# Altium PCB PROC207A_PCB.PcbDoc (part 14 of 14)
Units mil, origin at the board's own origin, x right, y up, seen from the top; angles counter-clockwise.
Board outline 4094.49 x 3724.79 mil, 8 copper layers (Top Layer, L2_GND1, L3_SIG1, L4_PWR1, L5_PWR2, L6_SIG2, L7_GND2, Bottom Layer), stack 58.1 mil thick; 584 components, 399 nets, 8440 pads, 5258 vias.
Unrouted connection lines stored in the file: 9.
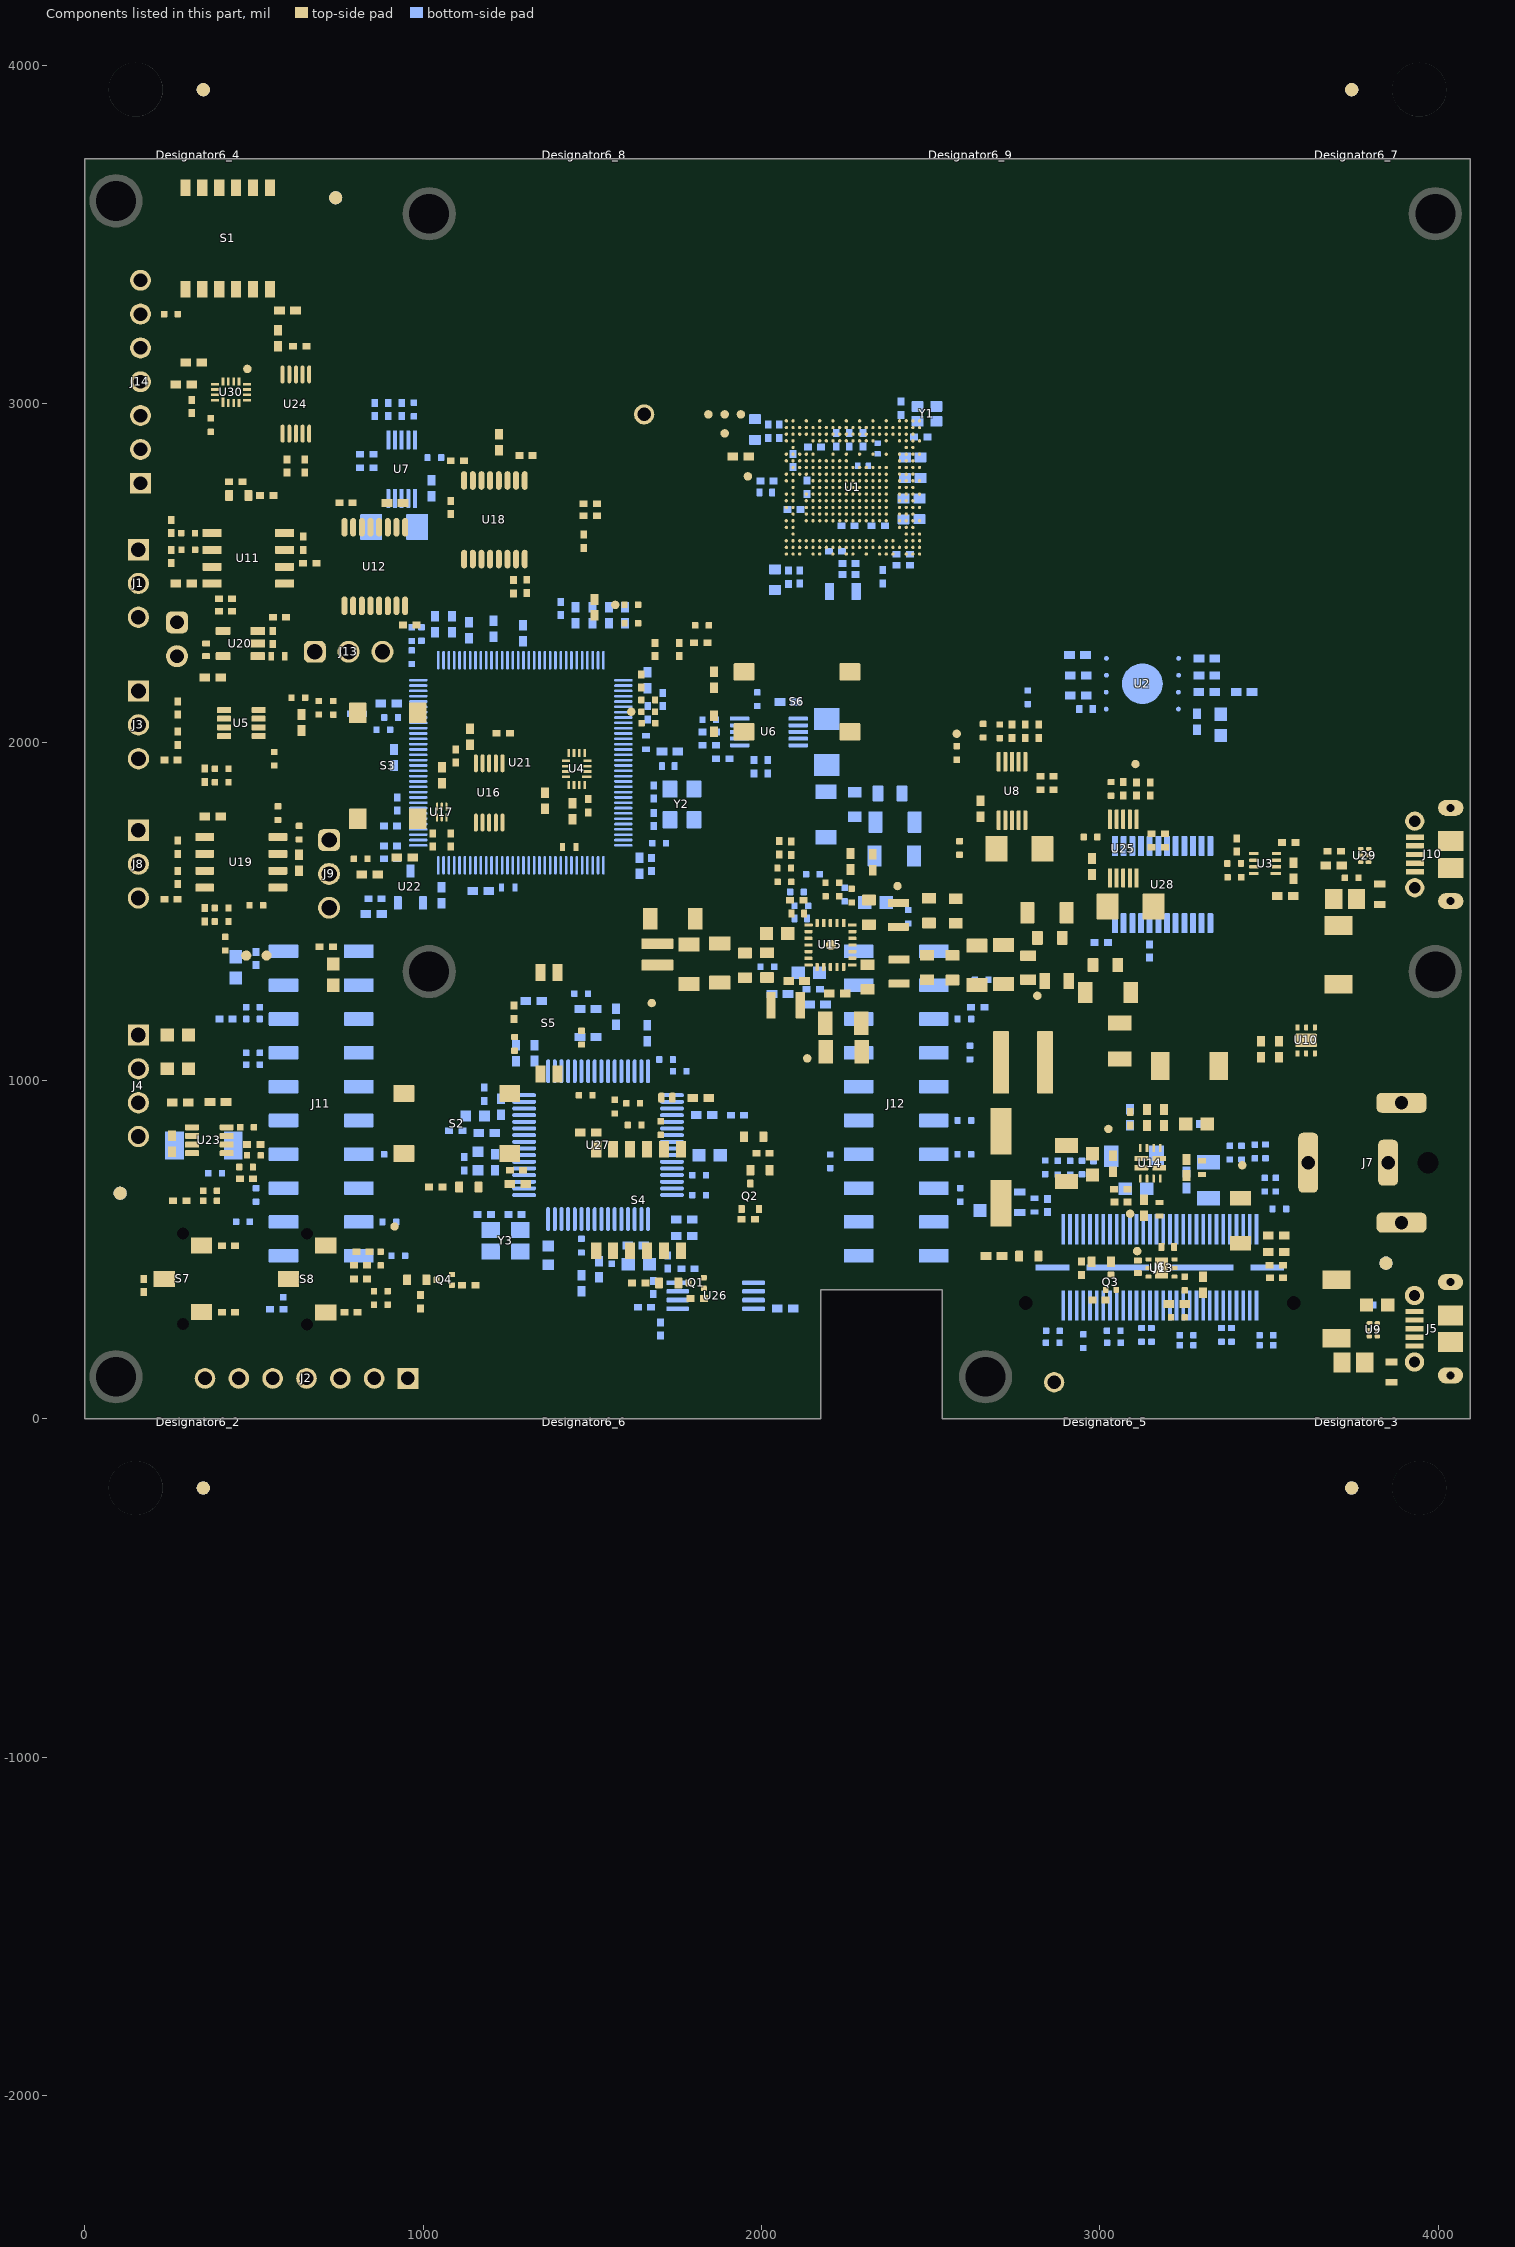
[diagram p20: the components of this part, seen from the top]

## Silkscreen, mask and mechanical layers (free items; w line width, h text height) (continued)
M10 Fab Notes:
  drawing of 251 lines, arcs and shapes, not listed
  text "1" at 349.4,8020.75 h70
  text "2" at 2845.07,8020.75 h70
  text "3" at 5334.41,8020.75 h70
  text "4" at 7841.08,8020.75 h70
  text "5" at 10340.07,8020.75 h70
  text "6" at 12845.07,8020.75 h70
  text "A" at -806.93,6877.75 h70
  text "A" at 13993.07,6877.75 h70
  text "DESIGN INFORMATION" at 11991.59,6340.43 h60
  text "4.0" at 12386.06,6211.03 h60
  text "MIN. TRACK WIDTH:" at 11347.03,6208.3 h60
  text "MIL" at 12598.03,6208.3 h60
  text "3.9" at 12383.52,6091.65 h60
  text "MIN. CLEARANCE:" at 11347.03,6084.17 h60
  text "MIL" at 12598.03,6084.17 h60
  text "MIN. VIA PAD SIZE:" at 11347.03,5960.05 h60
  text "13.77" at 12288.41,5958.58 h60
  text "MIL" at 12620.57,5951.25 h60
  text "EXTERNAL" at 12868.17,5832.74 h60
  text "0.127mm (5.0MIL)" at 12042.03,5830.15 h60
  text "MINIMUM ANNULAR RING" at 11017.8,5821.93 h60
  text "PER" at 11217.8,5711.8 h60
  text "IPC-D-275 CLASS 2 LEVEL C" at 11437.8,5711.8 h60
  text "MIL, HOLES" at 12926.03,5611.32 h60
  text "+/-" at 12533.57,5602.74 h60
  text "+/-" at 13387.57,5602.74 h60
  text "REGISTRATION TOLERANCES:" at 11017.8,5601.67 h60
  text "METAL" at 12217.57,5601.67 h60
  text "5" at 12793.77,5601.67 h60
  text "3" at 13626.77,5601.67 h60
  text "MIL" at 13743.03,5601.67 h60
  text "HOLE SIZE TOLERANCE (UNLESS OTHERWISE SPECIFIED):" at 11017.8,5503.36 h60
  text "+/-" at 13387.57,5500.48 h60
  text "3" at 13626.77,5499.42 h60
  text "MIL" at 13743.03,5499.42 h60
  text "MATERIAL:" at 10943.03,5361.77 h60
  text "FR-4 High Tg" at 11929.47,5233.25 h60
  text "X" at 12671.57,5228.25 h60
  text "REFER STACK-UP" at 13172.42,5227.66 h55
  text "FR-408" at 11364.03,5220.74 h60
  text "OTHER" at 12852.03,5220.74 h60
  text "X" at 12842.57,5080.26 h60
  text "62 MIL (1.6mm) +/-10%" at 11684.13,5077.71 h60
  text "59 MIL +/-10%" at 13264.57,5071.25 h45
  text "THICKNESS:" at 11017.8,5069.49 h60
  text "OTHER" at 12969.03,5069.49 h60
  text "TOLERANCE:" at 11017.8,4931.18 h60
  text "X" at 11866.03,4931.18 h60
  text "ANSI IPC-6012 TYPE 3 CLASS 2" at 12044.04,4931.18 h60
  text "OTHER +/-" at 12044.03,4786.99 h60
  text "BOW & TWIST:" at 11017.8,4641.8 h60
  text "X" at 11866.03,4641.8 h60
  text "ANSI IPC-6012 TYPE 3 CLASS 2" at 12044.04,4641.8 h60
  text "B" at -806.93,4497.75 h70
  text "B" at 13993.07,4497.75 h70
  text "OTHER +/-" at 12044.03,4495.1 h60
  text "DRILLING:" at 10943.03,4364.48 h60
  text "NOTES:" at 4526.86,4316.57 h60
  text "NC_DRILL FILES" at 12704.03,4259.29 h60
  text "REFERENCE:" at 11017.8,4255.36 h60
  text "AS SHOWN" at 11853.03,4255.36 h60
  text "X" at 12576.03,4255.36 h60
  text "X" at 11675.03,4255.26 h60
  text "1. BOARD SHALL MEET THE REQUIREMENTS OF UL-796E WITH FLAMMABILITY RATING OF MINIMUM 94V-0. UL LOGO," at 4553.62,4170.74 h60
  text "OTHER" at 13002.03,4113.1 h60
  text "PTH COPPER THICKNESS:" at 11017.47,4109.58 h60
  text "X" at 12156.71,4109.58 h60
  text "20-30 um" at 12284.7,4109.58 h60
  text "MANUFACTURER'S IDENTIFICATION AND DATE CODE LETTER SHALL BE RENDERED IN SILKSCREEN." at 4660.35,4071.75 h60
  text "BOARD FINISH:" at 10943.03,3961.98 h60
  text "2. VENDOR MAY ADJUST SOLDERMASK WHEREVER SOLDERMASK PADS ARE THE SAME SIZE (1:1) AS PER THE MANUFACTURING CAPABILITIES" at 4546.63,3945.96 h60
  text "SILKSCREEN:" at 11098.25,3851.85 h60
  text "X" at 12056.03,3851.85 h60
  text "TOP" at 12173.03,3851.85 h60
  text "X" at 12566.03,3851.85 h60
  text "BOTTOM" at 12684.03,3851.85 h60
  text "AND ALL OTHER SOLDER MASK PADS SHALL NOT BE MODIFIED, PROVIDED NO ADJACENT COPPER IS EXPOSED AND NO CONFLICT IS PRODUCED" at 4653.36,3846.97 h60
  text "WITH ANY STATED \"VIA TENTING/COVERING\" REQUIREMENTS." at 4653.36,3753.68 h60
  text "SILKSCREEN COLOR:" at 11098.25,3696.66 h60
  text "X" at 12055.03,3696.66 h60
  text "WHITE" at 12173.03,3696.66 h60
  text "OTHER" at 12684.03,3696.66 h60
  text "3. MANUFACTURER'S IDENTIFICATION,DATECODE LETTER SHALL BE SILKSCREENED ON SOLDER SIDE OF THE BOARD." at 4550.31,3635.58 h60
  text "GREEN" at 12304.03,3553.22 h60
  text "X" at 12778.03,3553.22 h60
  text "OTHER" at 12922.03,3553.22 h60
  text "RED" at 13294.57,3553.22 h60
  text "SOLDER RESIST COLOR:" at 11098.25,3546.35 h60
  text "4. TRACE WIDTH SHOULD BE ACCURATELY ETCHED. MAX TOLERANCE +/- 1 MIL." at 4545.35,3499.25 h60
  text "MATTE" at 12304.03,3398.96 h60
  text "SEMI-GLOSS" at 12921.57,3398.32 h60
  text "X" at 12777.63,3396.27 h60
  text "5. LAYER TO LAYER REGISTRATION SHALL BE WITHIN +/-2 MIL." at 4552.41,3375.14 h60
  text "6. REFER IMPEDANCE TABLE FOR IMPEDANCE CONTROL TRACES ON LAYER 1, 3, 6 & 8." at 4543.44,3254.27 h60
  text "IMMERSION GOLD (ENIG)" at 12004.03,3226.19 h60
  text "ENEPIG" at 13341.57,3218.97 h60
  text "SURFACE FINISH:" at 10943.03,3217.97 h60
  text "7. FOR ACCURACY OF THE ANTENNA DIMENSION, NEED TO BE MEASURE THE  ANTENNA DIMENSIONS ON ONE BOARD" at 4541.25,3102.51 h60
  text "IMM. SILVER" at 13118.96,3090.33 h60
  text "IMM. TIN/SILVER OR EQUIV" at 11272.57,3080.66 h60
  text "X" at 12526.45,3077.97 h60
  text "OTHER" at 12704.03,3076.72 h60
  text "8. ALL VIAS ARE TENTED ON BOTH SIDES UNLESS OTHERWISE SOLDER MASK OPENED IN GERBER." at 4534.83,2989.83 h60
  text "ARRAY/PANEL:" at 10943.03,2921.34 h60
  text "CUT AND TRIM PER M1 BOARD OUTLINE" at 12004.03,2913.12 h60
  text "9. VIA HOLE OFFSET SHALL BE WITHIN 1MILS OF ITS ORIGINAL LOCATION" at 4538.77,2874.22 h60
  text "10. 7 MIL VIA  SHOULD BE FILLED WITH CONDUCTIVE COPPER AND SURFACE SHOULD BE FLAT" at 4493.02,2782.48 h60
  text "X" at 11825.32,2778.38 h60
  text "N.C. ROUTE" at 12004.03,2777.15 h60
  text "V. SCORE" at 12870.03,2777.15 h60
  text "BGA AREA VIAS SHOULD BE CAPPED WITH COPPER PLATING TO ENSURE FLAT SURFACE" at 4662.87,2679.34 h60
  text "CERTIFICATION:" at 10943.03,2648.03 h60
  text "MATERIALS AND WORKMANSHIP FOR ALL PCBS" at 11668.03,2648.03 h60
  text "FLATNESS TOLERANCE FOR VIA ON PADS: +0.000 /- 0.001 INCHES ON BOTH SIDES." at 4661.13,2577.27 h60
  text "TO MEET OR EXCEED THE REQUIREMENTS OF:" at 11668.03,2553.96 h60
  text "X" at 11305.54,2425.33 h60
  text "ANSI IPC-A-600F CLASS ->" at 11433.53,2425.33 h60
  text "X" at 13081.54,2425.33 h60
  text "2" at 13191.53,2425.33 h60
  text "1" at 12876.53,2423.84 h60
  text "3" at 13545.53,2423.84 h60
  text "X" at 12117.54,2277.65 h60
  text "RoHS" at 12245.53,2277.65 h60
  text "OTHER" at 12889.93,2277.65 h60
  text "PER ORDER" at 13286.99,2277.65 h60
  text "ALL BOARDS MUST MEET OR EXCEED UL94-V0 REQUIREMENTS." at 10970.57,2123.82 h60
  text "C" at -806.93,2122.75 h70
  text "C" at 13993.07,2122.75 h70
  text "PCB MUST BEAR THE UL94V-0 UL REGISTERED MATERIAL ID NUMBER" at 10970.57,2007.76 h60
  text "ADDITIONAL REQUIREMENTS:" at 10943.03,1838.33 h60
  text "MICROSECTION:" at 11017.8,1731.21 h60
  text "YES" at 11923.53,1731.21 h60
  text "REQUIRED" at 12785.03,1586.87 h60
  text "BARE BOARD ELEC. TEST:" at 11017.8,1584.02 h60
  text "NONE" at 12323.53,1584.02 h60
  text "X" at 12667.03,1584.02 h60
  text "PER ORDER" at 13377.03,1584.02 h60
  text "XX MIL VIAS REQUIRE NON-CONDUCTIVE FILL AND PLANARIZE" at 11201.57,1438.25 h59
  text "XX MIL VIAS REQUIRE CONDUCTIVE FILL AND PLANARIZE" at 11192.57,1279.25 h60
  text "OUTER XX MIL TRACES REQUIRE 50 OHM SINGLE-ENDED IMPEDANCE" at 11187.71,1136.35 h58
  text "LAYER 1 & 6 (INNER LAYERS) XX MIL WIDE, XX MIL SPACE / TRACES REQUIRE 100 OHM DIFFERENTIAL IMPEDANCE" at 11226.57,886.25 h60
  text "PROJECT TITLE:" at 10953.07,261.75 h45
  text ".PRJ_Title" at 11003.07,128.43 h70
  text "DESIGNED FOR:" at 10953.07,-39.25 h45
  text ".PRJ_Customer" at 11003.07,-179.25 h70
  text "D" at -806.93,-247.25 h70
  text "D" at 13993.07,-247.25 h70
  text "FILE NAME:" at 10953.07,-339.25 h45
  text ".PCB_File_Name_No_Path" at 11003.07,-459.25 h70
  text "Texas Instruments (TI) and/or its licensors do not warrant the accuracy or completeness of this specification" at 5983.57,-621.09 h45
  text "ENGINEER:" at 10953.07,-629.25 h45
  text "LAYOUT BY:" at 12458.07,-629.25 h45
  text "or any information contained therein. TI and/or its licensors do not warrant that this design will meet" at 5938.58,-733.75 h45
  text ".PRJ_Engineer" at 11003.07,-784.24 h70
  text ".PCB_Layout" at 12508.57,-784.24 h70
  text "the specifications, will be suitable for your application or fit for any particular purpose, or will operate in" at 5938.58,-846.42 h45
  text ".Layer_Name" at 183.98,-874.87 h60
  text "ALTIUM DESIGNER VERSION:" at 12458.07,-939.25 h45
  text "an implementation. TI and/or its licensors do not warrant that the design is production worthy. You should" at 5938.58,-959.08 h45
  text "completely validate and test your design implementation to confirm the system functionality for your application." at 5983.57,-1071.75 h45
  text ".print_Scale" at 11003.07,-1072.57 h70
  text ".Application_BuildNumber" at 12508.57,-1072.57 h70
  text "1" at 349.4,-1279.25 h70
  text "2" at 2845.07,-1279.25 h70
  text "3" at 5334.41,-1279.25 h70
  text "4" at 7841.08,-1279.25 h70
  text "5" at 10340.07,-1279.25 h70
  text "6" at 12694.25,-1289.6 h70
M11 Gerber Information:
  lines w10: -682.43,-945.91 5917.57,-945.91 ; -682.43,-742.58 5919.57,-742.58 ; -682.43,-539.25 -682.43,-1149.25 3322.57,-1149.25 5919.57,-1149.25 5919.57,-539.25 -681.93,-539.25 -681.93,-1149.25 893.57,-1149.25 ; 1782.57,-1149.25 1782.57,-539.25 ; 3049.57,-742.58 3049.57,-539.25 ; 3889.57,-742.58 3889.57,-539.25 ; 4511.57,-1155.75 4511.57,-952.91
  text "ALL ARTWORK VIEWED FROM TOP SIDE" at -618.93,-671.41 h60
  text "BOARD #:" at 1857.57,-671.41 h60
  text ".PRJ_Number" at 2403.07,-671.41 h60
  text "REV:" at 3247.57,-671.41 h60
  text ".PCB_Rev" at 3539.07,-671.41 h60
  text "SVN REV:" at 4085.57,-671.41 h60
  text ".VersionControl_RevNumber" at 4591.57,-671.41 h60
  text "LAYER NAME =" at -618.93,-874.24 h60
  text "TID #:" at 1857.57,-874.75 h60
  text ".TID" at 2403.07,-874.75 h60
  text "PLOT NAME =" at -618.93,-1080.08 h60
  text ".plot_File_Name" at 186.57,-1080.08 h60
  text "GENERATED    :" at 1859.57,-1080.08 h60
  text ".Print_Date" at 2729.07,-1080.08 h60
  text ".Print_Time" at 3458.07,-1080.08 h60
  text "TEXAS INSTRUMENTS" at 4722.57,-1080.08 h60
M12 Stackup:
  drawing of 601 lines, arcs and shapes, not listed
  text "NOTE :" at 8331.23,7827.52 h60
  text "1. THIS IS AN IMPEDANCE CONTROLLED BOARD." at 8328.85,7700.44 h60
  text "2. EXTERNAL LAYER CU THICKNESSES ARE FINISHED THICKNESS AFTER PLATING." at 8328.85,7602.57 h60
  text "6" at 10048.98,7447.87 h60
  text "IMPEDANCE TABLE :" at 8892.6,7432.49 h80
  text "LAYER" at 8379.13,7323.14 h70
  text "TRACE WIDTH" at 8678.04,7322.3 h70
  text "SPACING" at 9163.04,7322.3 h70
  text "IMPEDANCE +/- 10%" at 9498.04,7322.3 h70
  text "REFERENCE LAYER" at 10223.04,7322.3 h70
  text "LAYER-2 (GND LAYER)" at 10182.92,7143.3 h65
  text "8.386 MILS" at 8742.92,7137.56 h65
  text "3.938 MILS" at 9157.24,7137.56 h65
  text "50 OHM" at 9617.92,7137.56 h65
  text "TOP" at 8420.48,7135.94 h70
  text "LAYER" at 8379.13,6945.5 h70
  text "TRACE WIDTH" at 8677.07,6944.65 h70
  text "SPACING" at 9162.07,6944.65 h70
  text "IMPEDANCE +/- 10%" at 9497.07,6944.65 h70
  text "REFERENCE LAYER" at 10222.07,6944.65 h70
  text "-" at 9281.1,6766.35 h65
  text "10.8 MILS" at 8734.57,6760.67 h65
  text "50 OHM" at 9671.63,6760.67 h65
  text "LAYER-2" at 10352.19,6760.55 h65
  text "TOP" at 8420.48,6759.04 h70
  text "-" at 9281.1,6585.89 h65
  text "BOTTOM" at 8370.42,6581.81 h60
  text "8.7 MILS" at 8749.62,6580.21 h65
  text "50 OHM" at 9671.63,6580.21 h65
  text "LAYER-7" at 10361.57,6580.21 h65
  text "-" at 9281.1,6400.89 h65
  text "LAYER-2, LAYER 7" at 10222.68,6398.21 h65
  text "6 MILS" at 8773.94,6393.7 h65
  text "50 OHM" at 9671.63,6393.7 h65
  text "L3 & L6" at 8363.23,6392.24 h70
  text "7.5 MILS" at 8749.68,6223.99 h65
  text "4 MILS" at 9197.23,6223.99 h65
  text "90 OHM" at 9671.27,6223.99 h65
  text "LAYER-2" at 10361.75,6223.87 h65
  text "TOP" at 8410.33,6222.36 h70
  text "BOTTOM" at 8370.42,6027.98 h60
  text "6 MILS" at 8773.94,6026.39 h65
  text "5 MILS" at 9197.98,6026.39 h65
  text "90 OHM" at 9671.27,6026.39 h65
  text "LAYER-7" at 10361.57,6026.39 h65
  text "LAYER-2, LAYER 4" at 10222.05,5847.69 h65
  text "5 MILS" at 8774,5843.19 h65
  text "5.9 MILS" at 9173.73,5843.19 h65
  text "90 OHM" at 9671.27,5843.19 h65
  text "L3" at 8449.93,5841.85 h70
  text "4.3 MILS" at 8748.99,5656.69 h65
  text "5.5 MILS" at 9173.73,5656.69 h65
  text "120 OHM" at 9656.46,5656.69 h65
  text "LAYER-2" at 10361.75,5656.57 h65
  text "TOP" at 8410.33,5655.06 h70
  text "5.8 MILS" at 8749.74,5483.99 h65
  text "4.2 MILS" at 9172.98,5483.99 h65
  text "100 OHM" at 9656.46,5483.99 h65
  text "LAYER-2" at 10361.75,5483.87 h65
  text "TOP" at 8410.33,5482.36 h70
  text "BOTTOM" at 8370.42,5287.98 h60
  text "5.9 MILS" at 8749.74,5286.39 h65
  text "3.9 MILS" at 9173.52,5286.39 h65
  text "100 OHM" at 9656.46,5286.39 h65
  text "LAYER-7" at 10361.57,5286.39 h65
  text "LAYER-2, LAYER 4" at 10222.05,5107.69 h65
  text "4.8 MILS" at 8748.99,5103.19 h65
  text "7.2 MILS" at 9173.67,5103.19 h65
  text "100 OHM" at 9656.46,5103.19 h65
  text "L3" at 8449.93,5101.85 h70
  text "LAYER STACK-UP :" at 4727.15,2285.49 h80
  text "Layer" at 4783.78,2184.88 h60
  text "Name" at 5193.69,2184.88 h60
  text "Material" at 6123.44,2184.88 h60
  text "Thickness" at 6983.2,2184.88 h60
  text "Constant" at 7633.04,2184.88 h60
  text "Board Layer Stack" at 8202.9,2184.88 h60
  text "Top Overlay" at 5193.69,2064.88 h60
  text "Top Solder" at 5193.69,1944.88 h60
  text "Solder Resist" at 6123.44,1944.88 h60
  text "0.80mil" at 6983.2,1944.88 h60
  text "1" at 7633.04,1944.88 h60
  text "1" at 4783.78,1824.88 h60
  text "Top Layer" at 5193.69,1824.88 h60
  text "1.60mil" at 6983.2,1824.88 h60
  text "Dielectric 1" at 5193.69,1704.88 h60
  text "RO3003" at 6123.44,1704.88 h60
  text "5.00mil" at 6983.2,1704.88 h60
  text "3" at 7633.04,1704.88 h60
  text "2" at 4783.78,1584.88 h60
  text "L2_GND1" at 5193.69,1584.88 h60
  text "1.40mil" at 6983.2,1584.88 h60
  text "Dielectric 2" at 5193.69,1464.88 h60
  text "PCL370HR" at 6123.44,1464.88 h60
  text "5.50mil" at 6983.2,1464.88 h60
  text "3.9" at 7633.04,1464.88 h60
  text "3" at 4783.78,1344.88 h60
  text "L3_SIG1" at 5193.69,1344.88 h60
  text "1.40mil" at 6983.2,1344.88 h60
  text "Dielectric 3" at 5193.69,1224.88 h60
  text "PCL370HR" at 6123.44,1224.88 h60
  text "10.00mil" at 6983.2,1224.88 h60
  text "4.25" at 7633.04,1224.88 h60
  text "4" at 4783.78,1104.88 h60
  text "L4_PWR1" at 5193.69,1104.88 h60
  text "1.40mil" at 6983.2,1104.88 h60
  text "Dielectric 4" at 5193.69,984.88 h60
  text "PCL370HR" at 6123.44,984.88 h60
  text "5.50mil" at 6983.2,984.88 h60
  text "3.9" at 7633.04,984.88 h60
  text "5" at 4783.78,864.88 h60
  text "L5_PWR2" at 5193.69,864.88 h60
  text "1.40mil" at 6983.2,864.88 h60
  text "Dielectric 5" at 5193.69,744.88 h60
  text "PCL370HR" at 6123.44,744.88 h60
  text "10.00mil" at 6983.2,744.88 h60
  text "4.25" at 7633.04,744.88 h60
  text "6" at 4783.78,624.88 h60
  text "L6_SIG2" at 5193.69,624.88 h60
  text "1.40mil" at 6983.2,624.88 h60
  text "Dielectric 6" at 5193.69,504.88 h60
  text "PCL370HR" at 6123.44,504.88 h60
  text "5.50mil" at 6983.2,504.88 h60
  text "3.9" at 7633.04,504.88 h60
  text "7" at 4783.78,384.88 h60
  text "L7_GND2" at 5193.69,384.88 h60
  text "1.40mil" at 6983.2,384.88 h60
  text "Dielectric 7" at 5193.69,264.88 h60
  text "PCL370HR" at 6123.44,264.88 h60
  text "5.00mil" at 6983.2,264.88 h60
  text "4.25" at 7633.04,264.88 h60
  text "8" at 4783.78,144.88 h60
  text "Bottom Layer" at 5193.69,144.88 h60
  text "1.60mil" at 6983.2,144.88 h60
  text "Bottom Solder" at 5193.69,24.88 h60
  text "Solder Resist" at 6123.44,24.88 h60
  text "0.80mil" at 6983.2,24.88 h60
  text "1" at 7633.04,24.88 h60
  text "Bottom Overlay" at 5193.69,-95.12 h60
  text "Total board thickness:" at 4783.78,-215.12 h60
  text "59.70mil" at 6983.2,-215.12 h60
  text ".Layer_Name" at 186.57,-874.24 h60
M13 Component Bodies Top:
  text ".Layer_Name" at 186.57,-874.24 h60
M14 Component Bodies Bottom:
  text ".Layer_Name" at 186.57,-874.24 h60
M15 Courtyards Top:
  text ".Layer_Name" at 186.57,-874.24 h60
M16 Courtyards Bottom:
  text ".Layer_Name" at 186.57,-874.24 h60
Drill Drawing:
  drawing of 185 lines, arcs and shapes, not listed
  text "Symbol" at -472.59,7628.05 h75.59
  text "Count" at 56.93,7628.05 h75.59
  text "Hole Size" at 748.68,7628.05 h75.59
  text "Plated" at 1828.77,7628.05 h75.59
  text "Hole Type" at 2358.3,7628.05 h75.59
  text "Drill Layer Pair" at 3127.12,7628.05 h75.59
  text "Hole Tolerance (+)" at 4396.13,7628.05 h75.59
  text "Hole Tolerance (-)" at 5794.69,7628.05 h75.59
  text "4306" at 56.93,7470.56 h62.99
  text "7.00mil (0.178mm)" at 748.68,7470.56 h62.99
  text "PTH" at 1828.77,7470.56 h62.99
  text "Round" at 2358.3,7470.56 h62.99
  text "Top Layer - L2_GND1" at 3127.12,7470.56 h62.99
  text "0.00mil (0.000mm)" at 4396.13,7470.56 h62.99
  text "0.00mil (0.000mm)" at 5794.69,7470.56 h62.99
  text "4306 Total" at 56.93,7313.07 h62.99
  text "Symbol" at -491.63,7093.66 h71.39
  text "Count" at 10.26,7093.66 h71.39
  text "Hole Size" at 654.79,7093.66 h71.39
  text "Hole Length" at 1794.95,7093.66 h71.39
  text "Plated" at 2905.38,7093.66 h71.39
  text "Hole Type" at 3407.27,7093.66 h71.39
  text "Drill Layer Pair" at 4135.17,7093.66 h71.39
  text "Hole Tolerance (+)" at 5622.29,7093.66 h71.39
  text "Hole Tolerance (-)" at 6944.95,7093.66 h71.39
  text "952" at 10.26,6944.92 h59.5
  text "8.00mil (0.203mm)" at 654.79,6944.92 h59.5
  text "-" at 1794.95,6944.92 h59.5
  text "PTH" at 2905.38,6944.92 h59.5
  text "Round" at 3407.27,6944.92 h59.5
  text "Top Layer - Bottom Layer" at 4135.17,6944.92 h59.5
  text "3.00mil (0.076mm)" at 5622.29,6944.92 h59.5
  text "3.00mil (0.076mm)" at 6944.95,6944.92 h59.5
  text "24" at 10.26,6796.19 h59.5
  text "19.69mil (0.500mm)" at 654.79,6796.19 h59.5
  text "-" at 1794.95,6796.19 h59.5
  text "NPTH" at 2905.38,6796.19 h59.5
  text "Round" at 3407.27,6796.19 h59.5
  text "Top Layer - Bottom Layer" at 4135.17,6796.19 h59.5
  text "E" at -520.54,6786.2 h66.11
  text "4" at 10.26,6647.45 h59.5
  text "23.62mil (0.600mm)" at 654.79,6647.45 h59.5
  text "51.18mil (1.300mm)" at 1794.95,6647.45 h59.5
  text "PTH" at 2905.38,6647.45 h59.5
  text "Slot" at 3407.27,6647.45 h59.5
  text "Top Layer - Bottom Layer" at 4135.17,6647.45 h59.5
  text "3.00mil (0.076mm)" at 5622.29,6647.45 h59.5
  text "3.00mil (0.076mm)" at 6944.95,6647.45 h59.5
  text "4" at 10.26,6498.71 h59.5
  text "33.47mil (0.850mm)" at 654.79,6498.71 h59.5
  text "-" at 1794.95,6498.71 h59.5
  text "PTH" at 2905.38,6498.71 h59.5
  text "Round" at 3407.27,6498.71 h59.5
  text "Top Layer - Bottom Layer" at 4135.17,6498.71 h59.5
  text "3.00mil (0.076mm)" at 5622.29,6498.71 h59.5
  text "3.00mil (0.076mm)" at 6944.95,6498.71 h59.5
  text "4" at 10.26,6349.97 h59.5
  text "35.43mil (0.900mm)" at 654.79,6349.97 h59.5
  text "-" at 1794.95,6349.97 h59.5
  text "NPTH" at 2905.38,6349.97 h59.5
  text "Round" at 3407.27,6349.97 h59.5
  text "Top Layer - Bottom Layer" at 4135.17,6349.97 h59.5
  text "3.00mil (0.076mm)" at 5622.29,6349.97 h59.5
  text "3.00mil (0.076mm)" at 6944.95,6349.97 h59.5
  text "1" at 10.26,6201.23 h59.5
  text "39.37mil (1.000mm)" at 654.79,6201.23 h59.5
  text "90.55mil (2.300mm)" at 1794.95,6201.23 h59.5
  text "PTH" at 2905.38,6201.23 h59.5
  text "Rectangle" at 3407.27,6201.23 h59.5
  text "Top Layer - Bottom Layer" at 4135.17,6201.23 h59.5
  text "3.00mil (0.076mm)" at 5622.29,6201.23 h59.5
  text "3.00mil (0.076mm)" at 6944.95,6201.23 h59.5
  text "B" at -520.54,6191.24 h66.11
  text "2" at 10.26,6052.49 h59.5
  text "39.37mil (1.000mm)" at 654.79,6052.49 h59.5
  text "98.43mil (2.500mm)" at 1794.95,6052.49 h59.5
  text "PTH" at 2905.38,6052.49 h59.5
  text "Rectangle" at 3407.27,6052.49 h59.5
  text "Top Layer - Bottom Layer" at 4135.17,6052.49 h59.5
  text "3.00mil (0.076mm)" at 5622.29,6052.49 h59.5
  text "3.00mil (0.076mm)" at 6944.95,6052.49 h59.5
  text "C" at -520.54,6042.5 h66.11
  text "1" at 10.26,5903.75 h59.5
  text "39.37mil (1.000mm)" at 654.79,5903.75 h59.5
  text "118.11mil (3.000mm)" at 1794.95,5903.75 h59.5
  text "PTH" at 2905.38,5903.75 h59.5
  text "Rectangle" at 3407.27,5903.75 h59.5
  text "Top Layer - Bottom Layer" at 4135.17,5903.75 h59.5
  text "3.00mil (0.076mm)" at 5622.29,5903.75 h59.5
  text "3.00mil (0.076mm)" at 6944.95,5903.75 h59.5
  text "11" at 10.26,5755.01 h59.5
  text "40.00mil (1.016mm)" at 654.79,5755.01 h59.5
  text "-" at 1794.95,5755.01 h59.5
  text "PTH" at 2905.38,5755.01 h59.5
  text "Round" at 3407.27,5755.01 h59.5
  text "Top Layer - Bottom Layer" at 4135.17,5755.01 h59.5
  text "3.00mil (0.076mm)" at 5622.29,5755.01 h59.5
  text "3.00mil (0.076mm)" at 6944.95,5755.01 h59.5
  text "2" at 10.26,5606.28 h59.5
  text "40.16mil (1.020mm)" at 654.79,5606.28 h59.5
  text "-" at 1794.95,5606.28 h59.5
  text "NPTH" at 2905.38,5606.28 h59.5
  text "Round" at 3407.27,5606.28 h59.5
  text "Top Layer - Bottom Layer" at 4135.17,5606.28 h59.5
  text "3.00mil (0.076mm)" at 5622.29,5606.28 h59.5
  text "3.00mil (0.076mm)" at 6944.95,5606.28 h59.5
  text "7" at 10.26,5457.54 h59.5
  text "40.16mil (1.020mm)" at 654.79,5457.54 h59.5
  text "-" at 1794.95,5457.54 h59.5
  text "PTH" at 2905.38,5457.54 h59.5
  text "Round" at 3407.27,5457.54 h59.5
  text "Top Layer - Bottom Layer" at 4135.17,5457.54 h59.5
  text "3.00mil (0.076mm)" at 5622.29,5457.54 h59.5
  text "3.00mil (0.076mm)" at 6944.95,5457.54 h59.5
  text "13" at 10.26,5308.8 h59.5
  text "43.31mil (1.100mm)" at 654.79,5308.8 h59.5
  text "-" at 1794.95,5308.8 h59.5
  text "PTH" at 2905.38,5308.8 h59.5
  text "Round" at 3407.27,5308.8 h59.5
  text "Top Layer - Bottom Layer" at 4135.17,5308.8 h59.5
  text "3.00mil (0.076mm)" at 5622.29,5308.8 h59.5
  text "3.00mil (0.076mm)" at 6944.95,5308.8 h59.5
  text "6" at 10.26,5160.06 h59.5
  text "45.28mil (1.150mm)" at 654.79,5160.06 h59.5
  text "-" at 1794.95,5160.06 h59.5
  text "PTH" at 2905.38,5160.06 h59.5
  text "Round" at 3407.27,5160.06 h59.5
  text "Top Layer - Bottom Layer" at 4135.17,5160.06 h59.5
  text "3.00mil (0.076mm)" at 5622.29,5160.06 h59.5
  text "3.00mil (0.076mm)" at 6944.95,5160.06 h59.5
  text "1" at 10.26,5011.32 h59.5
  text "62.99mil (1.600mm)" at 654.79,5011.32 h59.5
  text "-" at 1794.95,5011.32 h59.5
  text "NPTH" at 2905.38,5011.32 h59.5
  text "Round" at 3407.27,5011.32 h59.5
  text "Top Layer - Bottom Layer" at 4135.17,5011.32 h59.5
  text "3.00mil (0.076mm)" at 5622.29,5011.32 h59.5
  text "3.00mil (0.076mm)" at 6944.95,5011.32 h59.5
  text "D" at -520.54,5001.33 h66.11
  text "7" at 10.26,4862.58 h59.5
  text "118.11mil (3.000mm)" at 654.79,4862.58 h59.5
  text "-" at 1794.95,4862.58 h59.5
  text "PTH" at 2905.38,4862.58 h59.5
  text "Round" at 3407.27,4862.58 h59.5
  text "Top Layer - Bottom Layer" at 4135.17,4862.58 h59.5
  text "3.00mil (0.076mm)" at 5622.29,4862.58 h59.5
  text "3.00mil (0.076mm)" at 6944.95,4862.58 h59.5
  text "4" at 10.26,4713.84 h59.5
  text "160.00mil (4.064mm)" at 654.79,4713.84 h59.5
  text "-" at 1794.95,4713.84 h59.5
  text "NPTH" at 2905.38,4713.84 h59.5
  text "Round" at 3407.27,4713.84 h59.5
  text "Top Layer - Bottom Layer" at 4135.17,4713.84 h59.5
  text "2.00mil (0.051mm)" at 5622.29,4713.84 h59.5
  text "2.00mil (0.051mm)" at 6944.95,4713.84 h59.5
  text "1043 Total" at 10.26,4565.11 h59.5
  text "Slot definitions :" at -491.63,4421.18 h59.5
  text "Routed Path Length" at 532.61,4421.18 h59.5
  text "= Calculated from tool start centre position to tool end centre position." at 1626.24,4421.18 h59.5
  text "Hole Length" at 532.61,4321.88 h59.5
  text "= Routed Path Length + Tool Size = Slot length as defined in the PCB layout" at 1219.82,4321.88 h59.5
  text ".Layer_Name" at 186.57,-874.24 h60
M17 Embedded Cavity:
  text ".Layer_Name" at 186.57,-874.24 h60
M18 Embedded Assembly:
  text ".Layer_Name" at 186.57,-874.24 h60
M19 Embedded Keepout:
  text ".Layer_Name" at 186.57,-874.24 h60
DCA1000:
  drawing of 11001 lines, arcs and shapes, not listed
6888_RX:
  drawing of 324 lines, arcs and shapes, not listed
PROC074B-PCB_dxf:
  drawing of 11227 lines, arcs and shapes, not listed
6888_TX:
  drawing of 18911 lines, arcs and shapes, not listed

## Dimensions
4094.49,3724.79 to 4094.49,3803.57 on M2 Board Dimensions
0,3724.79 to 0,0 on M2 Board Dimensions
0,4079.13 to 0,-354.34 on M2 Board Dimensions
0,-78.74 to 0,-354.34 on M2 Board Dimensions
2174.49,0 to 2534.49,0 on M2 Board Dimensions
2534.49,381.95 to 2534.49,0 on M2 Board Dimensions
0,4079.13 to 4094.49,4079.13 on M2 Board Dimensions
